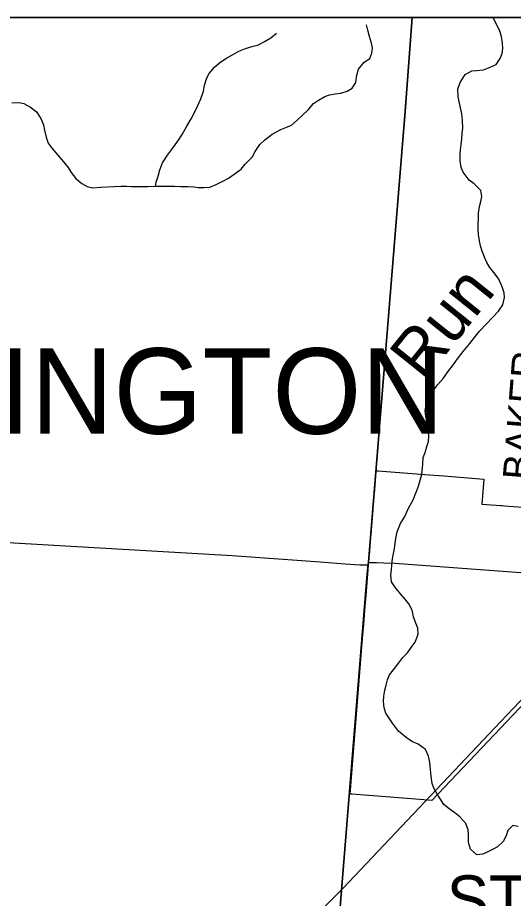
# Model space of a CAD drawing. Extents: x 0 to 42.5, y 0 to 22.
# Drawn here: x 5.216 to 5.71, y 20.022 to 20.9 of the extents above; entities that cross this region are included whole.
import ezdxf

# ---------------------------------------------------------------- set-up
doc = ezdxf.new("R2010")
doc.units = 0
for name, color, linetype in [('GM_X_Corporation', 7, 'Continuous'), ('GM_X_Corporation_Text', 7, 'Continuous'), ('GM_X_County_Road', 7, 'Continuous'), ('GM_X_Interchange_Ramps', 7, 'Continuous'), ('GM_X_Minor_River', 7, 'Continuous'), ('GM_X_Minor_River_Text', 7, 'Continuous'), ('GM_X_Rail_Line', 7, 'Continuous'), ('GM_X_Township_Road_Text', 7, 'Continuous'), ('GM_X_Township_Text', 7, 'Continuous'), ('SH_Cut_Line', 7, 'Continuous'), ('SH_Data', 7, 'Continuous')]:
    doc.layers.add(name, color=color, linetype=linetype)

msp = doc.modelspace()

# ---------------------------------------------------------------- linework, layer by layer
at = {"layer": 'GM_X_Corporation'}
msp.add_lwpolyline([(5.72239, 20.21799), (5.62902, 20.11961), (5.6169, 20.12059), (5.5492, 20.12608), (5.54751, 20.12621), (5.56005, 20.28106), (5.5612, 20.29522), (5.56235, 20.30937), (5.56388, 20.32824), (5.56633, 20.35846), (5.56711, 20.36789), (5.56803, 20.37901), (5.56881, 20.38846), (5.56926, 20.39393), (5.57055, 20.40952), (5.57107, 20.41574), (5.57222, 20.42965), (5.5737, 20.44752), (5.57378, 20.44845), (5.57547, 20.44832), (5.62208, 20.44467), (5.64111, 20.44318), (5.68069, 20.44008), (5.6787, 20.41522), (5.68361, 20.41484), (5.69776, 20.41375), (5.69904, 20.41365), (5.70153, 20.41346), (5.71947, 20.41207)], dxfattribs=at)
at = {"layer": 'GM_X_County_Road'}
msp.add_line((5.56574, 20.3547), (5.56596, 20.35703), dxfattribs=at)
for points in [[(5.56596, 20.35703), (5.60262, 20.80654), (5.6097, 20.9)], [(3.99308, 20.20605), (4.18641, 20.19195), (4.25615, 20.1882), (4.27629, 20.19063), (4.35151, 20.25076), (4.53663, 20.37454), (4.57824, 20.40887), (4.60018, 20.41726), (4.78505, 20.40446), (5.0521, 20.38596), (5.43022, 20.36402), (5.51787, 20.35753), (5.54254, 20.35547), (5.55726, 20.35474), (5.56574, 20.3547)], [(5.56596, 20.35703), (5.57381, 20.35696), (5.58125, 20.35675), (5.59211, 20.35615), (5.73081, 20.34586), (5.75511, 20.3445), (5.82184, 20.33927), (5.82753, 20.33791), (5.83304, 20.3374), (5.86327, 20.33478), (5.92331, 20.33097), (5.94373, 20.32919), (5.95398, 20.32846), (5.97736, 20.32682), (5.98191, 20.32636)], [(5.52537, 19.85349), (5.53547, 19.98446), (5.54617, 20.11632), (5.56485, 20.34535), (5.56574, 20.3547)]]:
    msp.add_lwpolyline(points, dxfattribs=at)
at = {"layer": 'GM_X_Interchange_Ramps'}
for points in [[(5.48884, 19.405), (5.50057, 19.55251), (5.51061, 19.66936), (5.5156, 19.73605), (5.52526, 19.85376), (5.53536, 19.98472), (5.54606, 20.11658), (5.56474, 20.34561), (5.56563, 20.35496), (5.56586, 20.35729), (5.60252, 20.8068), (5.60957, 20.9), (3.50401, 20.9), (3.49253, 20.65067), (3.48511, 20.52333), (3.47328, 20.34399), (3.47315, 20.34124), (3.46843, 20.23651), (3.46832, 20.23391), (3.43715, 19.68433), (3.40756, 19.23914)], [(8.59772, 20.9), (5.60957, 20.9), (5.60252, 20.8068), (5.56586, 20.35729), (5.56563, 20.35496), (5.56474, 20.34561), (5.54606, 20.11658), (5.53536, 19.98472), (5.52526, 19.85376), (5.5156, 19.73605), (5.51061, 19.66936), (5.50057, 19.55251), (5.48884, 19.405)]]:
    msp.add_lwpolyline(points, dxfattribs=at)
at = {"layer": 'GM_X_Minor_River'}
for points in [[(5.21081, 20.81515), (5.21783, 20.81534), (5.22257, 20.81438), (5.22939, 20.81077), (5.23526, 20.8062), (5.23961, 20.79954), (5.24225, 20.79308), (5.24319, 20.78794), (5.24488, 20.78091), (5.24696, 20.77482), (5.25093, 20.7695), (5.25661, 20.76303), (5.26058, 20.75827), (5.26664, 20.75048), (5.26966, 20.74553), (5.27439, 20.73982), (5.28026, 20.73469), (5.28557, 20.73183), (5.29087, 20.7305), (5.29922, 20.73106), (5.3123, 20.73181), (5.31913, 20.732), (5.325, 20.732), (5.32974, 20.7318), (5.336, 20.73161), (5.34624, 20.7316), (5.35363, 20.73198), (5.36653, 20.73197), (5.37278, 20.73197), (5.37904, 20.73177), (5.38568, 20.73177), (5.39193, 20.73119), (5.39667, 20.73081), (5.40179, 20.73081), (5.40786, 20.73118), (5.41412, 20.73384), (5.42152, 20.73726), (5.42664, 20.74011), (5.43215, 20.74391), (5.43898, 20.74903), (5.44297, 20.75378), (5.45, 20.761), (5.45304, 20.76652), (5.45779, 20.77355), (5.46273, 20.7783), (5.46994, 20.784), (5.47867, 20.78836), (5.48361, 20.79045), (5.48911, 20.79292), (5.49499, 20.79786), (5.49974, 20.80242), (5.50582, 20.80812), (5.51114, 20.81439), (5.51607, 20.81762), (5.52234, 20.82141), (5.52708, 20.82312), (5.53277, 20.82388), (5.53846, 20.82483), (5.54453, 20.82653), (5.54965, 20.82976), (5.55326, 20.83527), (5.55441, 20.84269), (5.55613, 20.84877), (5.56145, 20.85561), (5.56733, 20.85922), (5.56924, 20.86454), (5.56982, 20.86986), (5.56907, 20.87462), (5.56699, 20.88108), (5.5653, 20.88755), (5.56379, 20.89287)], [(5.62407, 20.4726), (5.62565, 20.47752), (5.62609, 20.48302), (5.62542, 20.49044), (5.62399, 20.49768), (5.62291, 20.50244), (5.62241, 20.50852), (5.62342, 20.51421), (5.62482, 20.52047), (5.63003, 20.52782), (5.63484, 20.53423), (5.64022, 20.54025), (5.64504, 20.54704), (5.65043, 20.55439), (5.65467, 20.56004), (5.66025, 20.5672), (5.66679, 20.5753), (5.67238, 20.58246), (5.67641, 20.58736), (5.68313, 20.5945), (5.68928, 20.60128), (5.69542, 20.60729), (5.69966, 20.61389), (5.70126, 20.62091), (5.70094, 20.62585), (5.69892, 20.63157), (5.6956, 20.63921), (5.69205, 20.64419), (5.68683, 20.65108), (5.68385, 20.65587), (5.68145, 20.66121), (5.67905, 20.66732), (5.67741, 20.67247), (5.67633, 20.67742), (5.67545, 20.6837), (5.67513, 20.68883), (5.6752, 20.69453), (5.67545, 20.69985), (5.67551, 20.70517), (5.67635, 20.71181), (5.67773, 20.71674), (5.67874, 20.72166), (5.67767, 20.72776), (5.6713, 20.73429), (5.66623, 20.73814), (5.66025, 20.74581), (5.65822, 20.75058), (5.65716, 20.75724), (5.65723, 20.76351), (5.65767, 20.76826), (5.6583, 20.77357), (5.65894, 20.77926), (5.65938, 20.78477), (5.66001, 20.78989), (5.65971, 20.7973), (5.65885, 20.80415), (5.65759, 20.81006), (5.65633, 20.81634), (5.65525, 20.8211), (5.65496, 20.8289), (5.65712, 20.83533), (5.66215, 20.84345), (5.66883, 20.84699), (5.67357, 20.84731), (5.6804, 20.848), (5.68707, 20.85059), (5.69317, 20.85337), (5.69703, 20.85922), (5.69917, 20.86432), (5.6998, 20.86907), (5.69948, 20.87458), (5.69842, 20.88105), (5.69659, 20.88639), (5.68999, 20.9)], [(5.35363, 20.73198), (5.3544, 20.73597), (5.3563, 20.74205), (5.35821, 20.74833), (5.36088, 20.75536), (5.36563, 20.76277), (5.36962, 20.76809), (5.37323, 20.77322), (5.37684, 20.77797), (5.38026, 20.78348), (5.38502, 20.79165), (5.3892, 20.79907), (5.39262, 20.80534), (5.39605, 20.81237), (5.3989, 20.81902), (5.40157, 20.82682), (5.40272, 20.83252), (5.40462, 20.83898), (5.40691, 20.84411), (5.41261, 20.85057), (5.41754, 20.85494), (5.42381, 20.85931), (5.42988, 20.86273), (5.43671, 20.86672), (5.44335, 20.86937), (5.45094, 20.87146), (5.45625, 20.87298), (5.46251, 20.87621), (5.46859, 20.87982), (5.47428, 20.88437)], [(5.71502, 20.09387), (5.70972, 20.09469), (5.70474, 20.08999), (5.70297, 20.0845), (5.70006, 20.07902), (5.6945, 20.07357), (5.68954, 20.07097), (5.68477, 20.06855), (5.67981, 20.06613), (5.67374, 20.06544), (5.66755, 20.0714), (5.66554, 20.07788), (5.66544, 20.08529), (5.66531, 20.09042), (5.66273, 20.09691), (5.65693, 20.10362), (5.65205, 20.10748), (5.64622, 20.11153), (5.64096, 20.11577), (5.63686, 20.12208), (5.63388, 20.12687), (5.6311, 20.13203), (5.62945, 20.1368), (5.6282, 20.14403), (5.62771, 20.1505), (5.62704, 20.15772), (5.62559, 20.16401), (5.62264, 20.1705), (5.61531, 20.1759), (5.60908, 20.17844), (5.60344, 20.18249), (5.59593, 20.18885), (5.58976, 20.1967), (5.5866, 20.20168), (5.58325, 20.20684), (5.58141, 20.21218), (5.58073, 20.21846), (5.58117, 20.22378), (5.58219, 20.22985), (5.58338, 20.23477), (5.58477, 20.24008), (5.58691, 20.245), (5.59173, 20.2514), (5.59615, 20.25686), (5.6002, 20.26214), (5.6048, 20.26703), (5.60847, 20.27231), (5.61251, 20.27759), (5.61545, 20.28553), (5.61514, 20.29162), (5.61292, 20.29658), (5.61091, 20.30268), (5.60928, 20.30954), (5.60613, 20.31585), (5.60202, 20.32064), (5.59772, 20.32582), (5.5923, 20.33253), (5.58894, 20.3377), (5.58827, 20.34454), (5.5887, 20.34967), (5.58914, 20.35441), (5.58997, 20.36049), (5.59098, 20.36579), (5.59198, 20.37091), (5.59242, 20.37585), (5.59324, 20.38078), (5.59445, 20.38742), (5.59796, 20.39574), (5.60203, 20.40272), (5.60573, 20.41123), (5.61056, 20.41935), (5.61349, 20.42692), (5.61565, 20.43317), (5.61743, 20.43904), (5.6192, 20.44472), (5.62008, 20.45497), (5.62053, 20.46161), (5.6223, 20.46672), (5.62407, 20.4726)]]:
    msp.add_lwpolyline(points, dxfattribs=at)
at = {"layer": 'GM_X_Rail_Line'}
for points in [[(5.54064, 20.03224), (5.69761, 20.19849), (6.00325, 20.52048), (6.35749, 20.89191), (6.36519, 20.9)], [(2.61877, 19.97568), (2.65326, 19.99211), (2.69136, 20.00655), (2.71989, 20.01446), (2.74816, 20.0195), (2.77247, 20.02118), (2.80231, 20.02106), (2.83481, 20.01941), (2.91733, 20.01403), (3.26401, 19.99461), (3.61724, 19.97619), (3.94708, 19.95463), (4.29937, 19.93411), (4.5956, 19.91226), (5.05555, 19.8842), (5.17532, 19.87894), (5.25442, 19.87492), (5.30129, 19.87455), (5.33367, 19.88019), (5.36925, 19.89196), (5.40278, 19.90809), (5.43829, 19.93181), (5.47396, 19.96523), (5.54064, 20.03224)]]:
    msp.add_lwpolyline(points, dxfattribs=at)
at = {"layer": 'SH_Cut_Line'}
for points in [[(5.48884, 19.405), (5.50057, 19.55251), (5.51061, 19.66936), (5.5156, 19.73605), (5.52526, 19.85376), (5.53536, 19.98472), (5.54606, 20.11658), (5.56474, 20.34561), (5.56563, 20.35496), (5.56586, 20.35729), (5.60252, 20.8068), (5.60957, 20.9), (2.1, 20.9), (2.1, 16.00757)], [(8.9, 20.9), (5.60957, 20.9), (5.60252, 20.8068), (5.56586, 20.35729), (5.56563, 20.35496), (5.56474, 20.34561), (5.54606, 20.11658), (5.53536, 19.98472), (5.52526, 19.85376), (5.5156, 19.73605), (5.51061, 19.66936), (5.50057, 19.55251), (5.48884, 19.405)]]:
    msp.add_lwpolyline(points, dxfattribs=at)
at = {"layer": 'SH_Data'}
msp.add_line((2.1, 20.9), (8.9, 20.9), dxfattribs=at)

# ---------------------------------------------------------------- texts
at = {"layer": 'GM_X_Corporation_Text'}
msp.add_text('STOUTSVILLE', height=0.0473485, rotation=0.00001, dxfattribs=at).set_placement((5.64379, 19.99777))
at = {"layer": 'GM_X_Minor_River_Text'}
msp.add_text('Run', height=0.047347, rotation=51.2265, dxfattribs=at).set_placement((5.62091, 20.53641))
at = {"layer": 'GM_X_Township_Road_Text'}
msp.add_text('BAKER', height=0.028409, rotation=85.52347, dxfattribs=at).set_placement((5.72788, 20.43835))
at = {"layer": 'GM_X_Township_Text'}
msp.add_text('WASHINGTON', height=0.085227, rotation=0.00001, dxfattribs=at).set_placement((4.85605, 20.48522))

doc.saveas('drawing.dxf')
